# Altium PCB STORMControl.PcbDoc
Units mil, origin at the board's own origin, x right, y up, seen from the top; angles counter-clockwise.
Board outline 3700 x 3210 mil, 2 copper layers (Top Layer, Bottom Layer); 76 components, 43 nets, 234 pads, 25 vias.
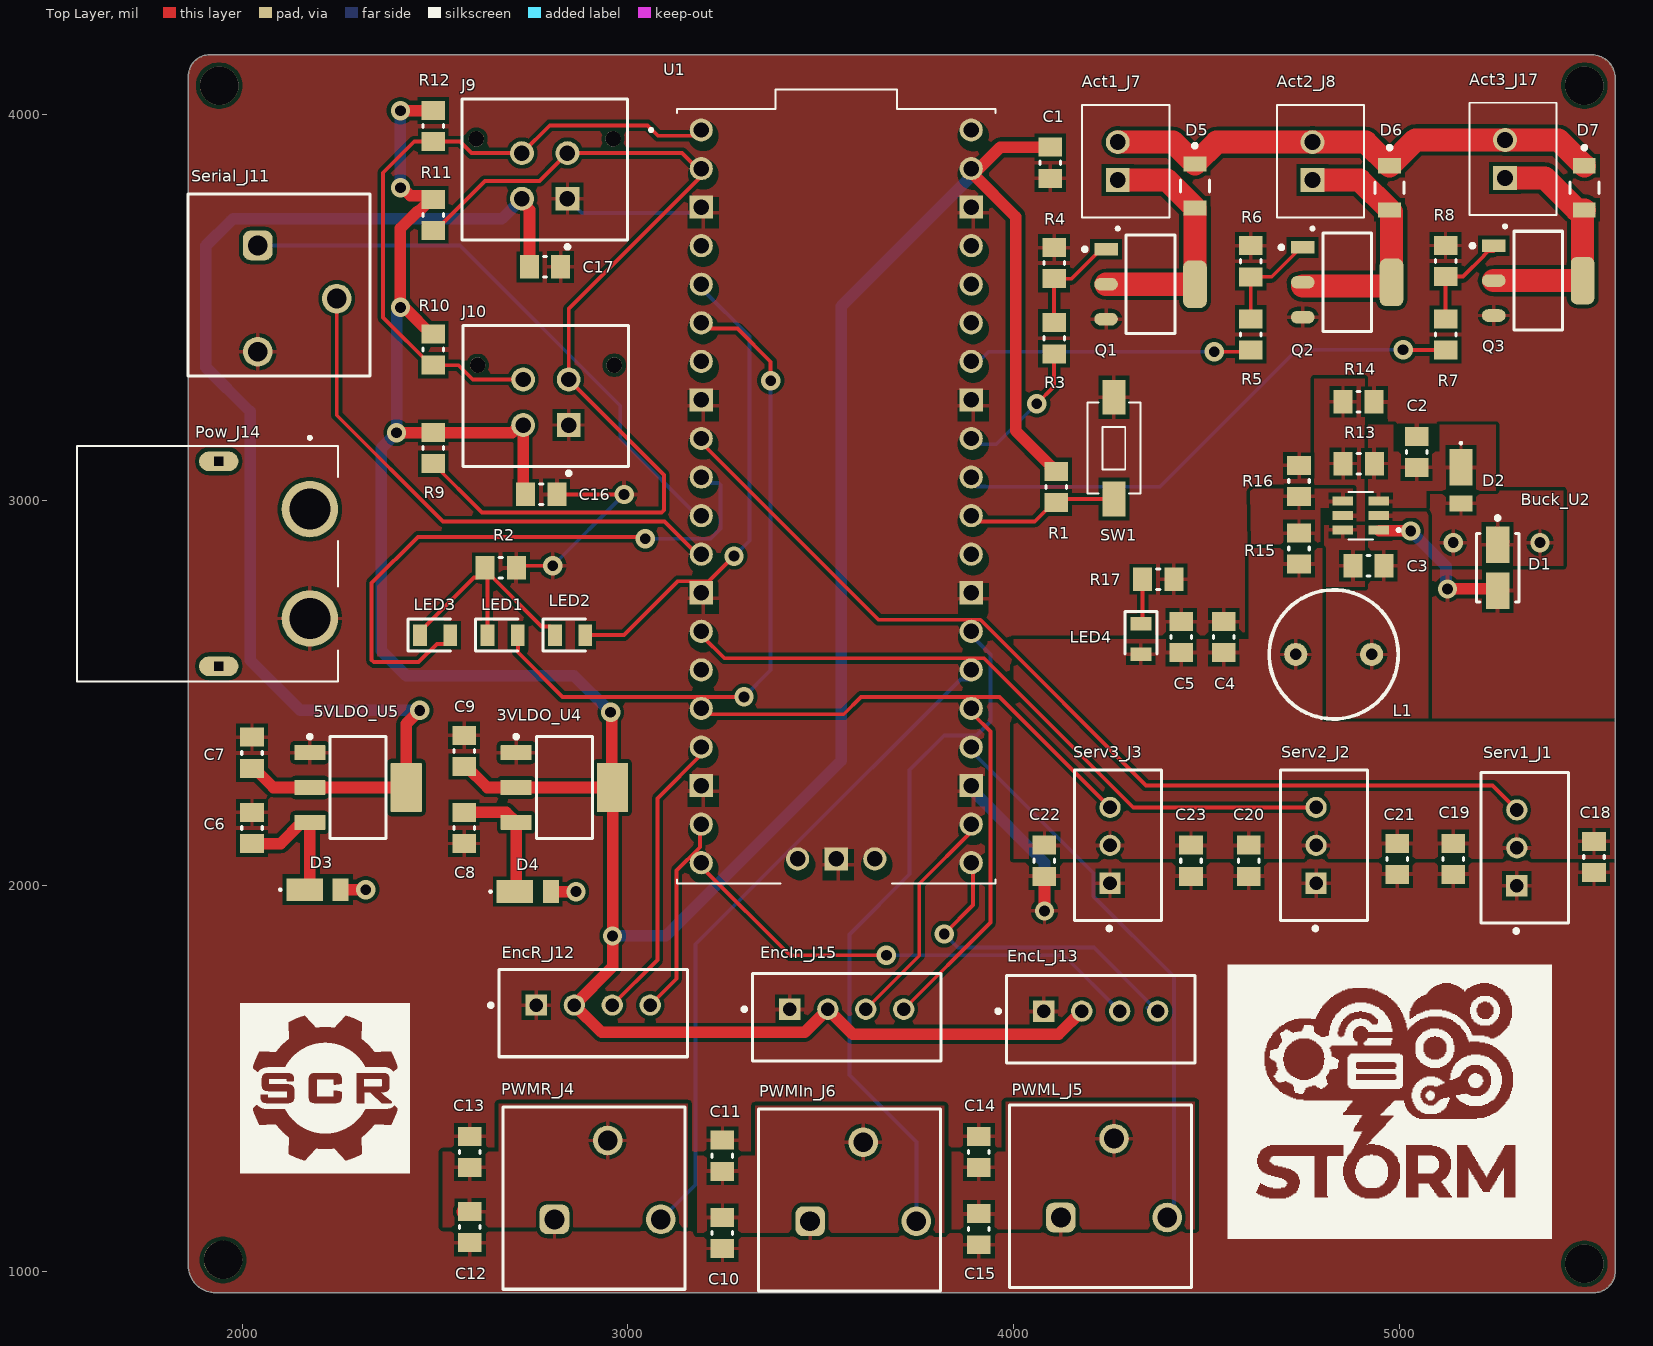
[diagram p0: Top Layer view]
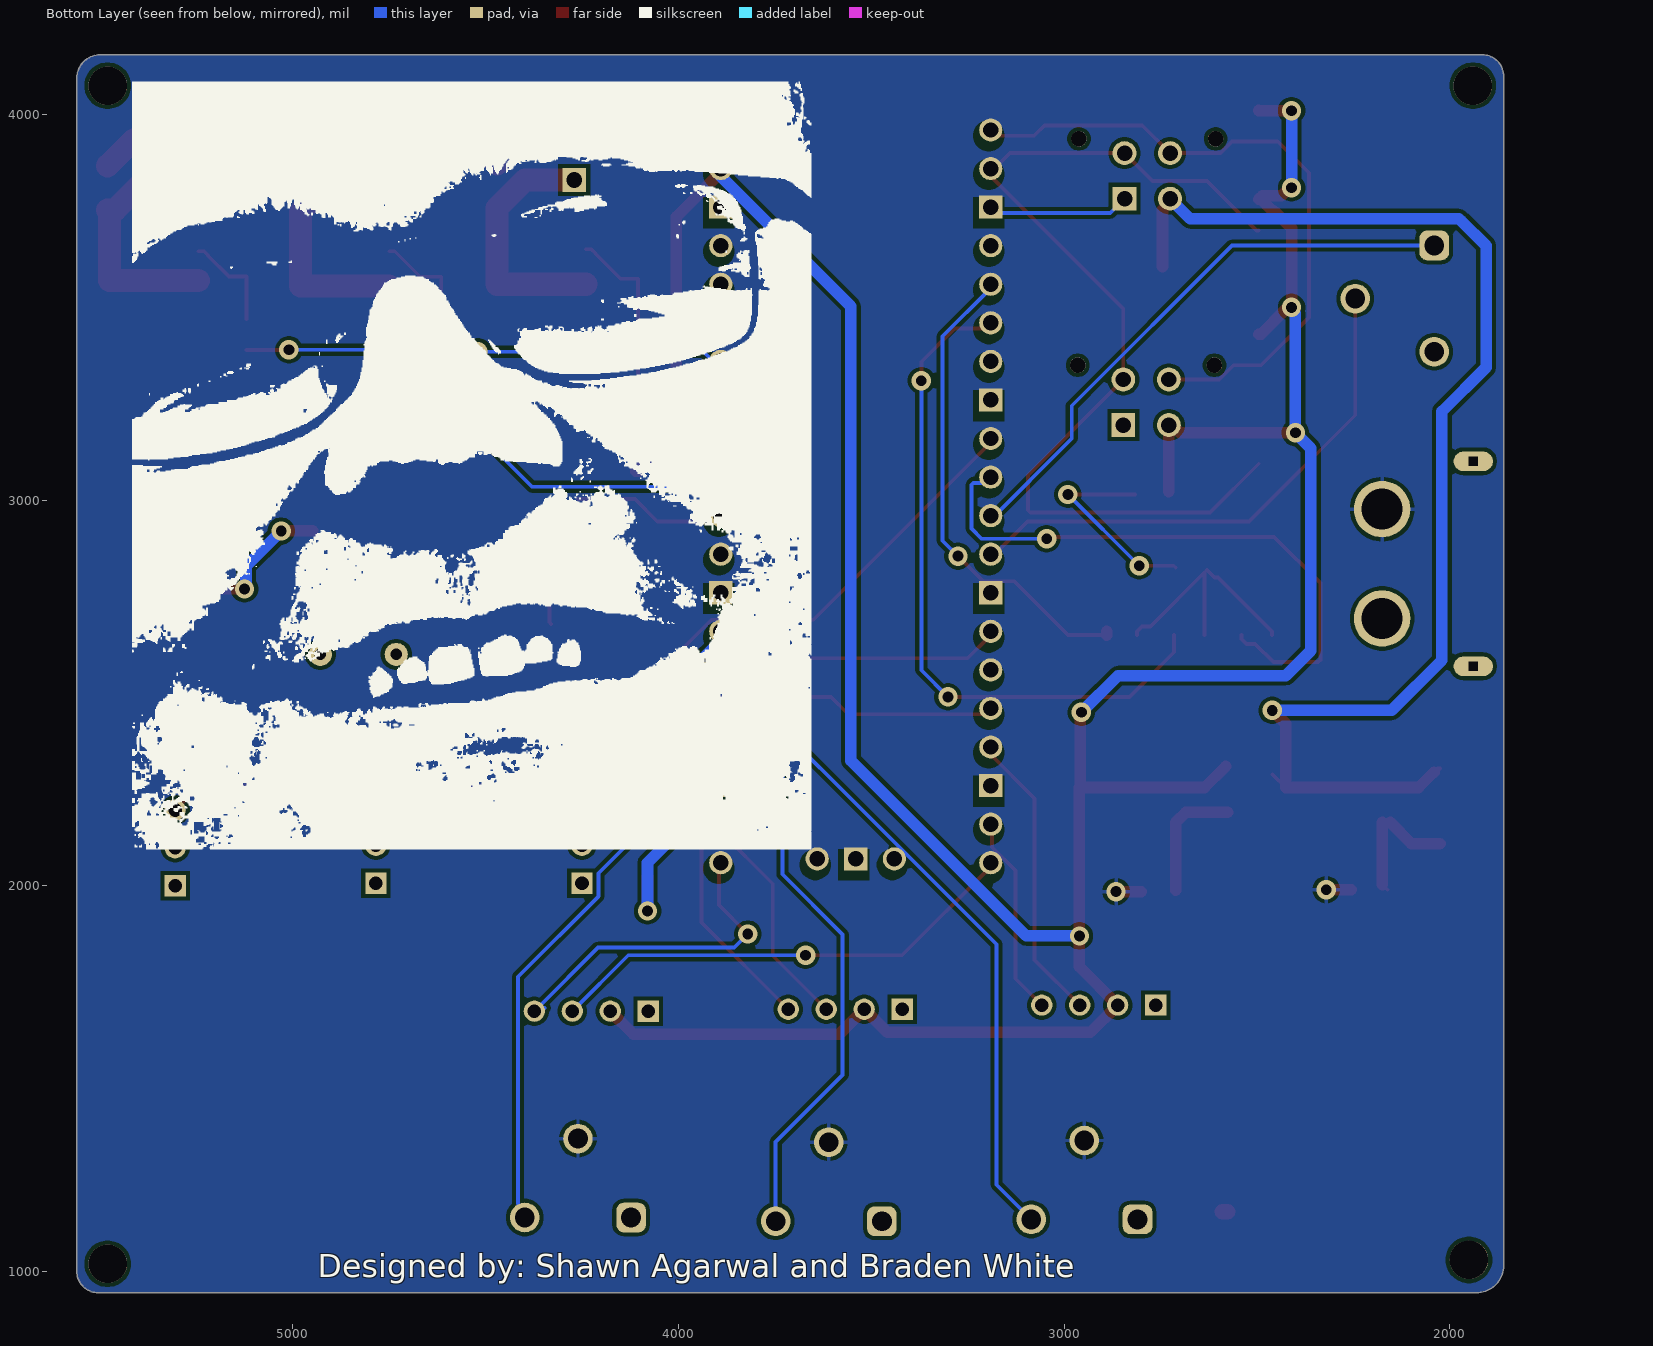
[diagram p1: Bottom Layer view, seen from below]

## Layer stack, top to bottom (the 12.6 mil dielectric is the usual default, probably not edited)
Top Solder: solder mask 0.4, Solder Resist, Dk 3.5
Top Layer: signal copper 1.4
Dielectric 1: dielectric 12.6, FR-4, Dk 4.8
Bottom Layer: signal copper 1.4
Bottom Solder: solder mask 0.4, Solder Resist, Dk 3.5

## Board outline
1860,1015 1860,4100 cw(c1915,4100) 1915,4155 5500,4155 cw(c5500,4095) 5560,4095 5560,1000 cw(c5505,1000) 5505,945 1930,945 cw(c1930,1015)

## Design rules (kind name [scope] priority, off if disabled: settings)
BoardOutlineClearance [All] p1: gap=0.75 ignorepadtopadclearanceinfootprint=FALSE
Clearance [All] p1: gap=10 ignorepadtopadclearanceinfootprint=FALSE
PolygonConnect [All] p1: connectstyle=Relief reliefconductorwidth=10 reliefentries=4 polygonreliefangle="90 Angle" airgapwidth=10
RoutingVias [All] p1: holewidth=28 width=50 viastyle="Through Hole" minholewidth=28 minwidth=50 maxholewidth=28 maxwidth=50
SolderMaskExpansion SolverMaskExpansion_Via [IsVia] p1: expansion=4 istentingtop=TRUE
SolderMaskExpansion [All] p2: expansion=4 istentingtop=FALSE
SupplyNets "Schematic Supply Nets_4" [InNet('+5')] p1: voltage=0.000
SupplyNets "Schematic Supply Nets_3" [InNet('+7')] p2: voltage=0.000
SupplyNets "Schematic Supply Nets_2" [InNet('GND')] p3: voltage=0.000
SupplyNets "Schematic Supply Nets_1" [InNet('+3.3')] p4: voltage=0.000
SupplyNets "Schematic Supply Nets" [InNet('+12')] p5: voltage=0.000
Width [All] p1: maxlimit=80 minlimit=10 preferedwidth=10 minimp=50.000000 maximp=50.000000 favimp=50.000000
30 further rules are at their usual default settings.

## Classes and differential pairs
component class U_power: 3VLDO_U4 5VLDO_U5 Buck_U2 C2 C3 C4 C5 C6 C7 C8 C9 D1 D2 D3 D4 L1 LED4 R13 R14 R15 R16 R17
component class U_pico: C1 LED1 LED2 LED3 Q1 Q2 Q3 R1 R2 R3 R4 R5 R6 R7 R8 SW1 U1
component class U_interfaces: Act1_J7 Act2_J8 Act3_J17 C10 C11 C12 C13 C14 C15 C16 C17 C18 C19 C20 C21 C22 C23 D5 D6 D7 EncIn_J15 EncL_J13 EncR_J12 J9 J10 Pow_J14 PWMIn_J6 PWML_J5 PWMR_J4 R9 R10 R11 R12 Serial_J11 Serv1_J1 Serv2_J2 Serv3_J3

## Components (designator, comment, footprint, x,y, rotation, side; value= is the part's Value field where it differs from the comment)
3VLDO_U4 "REG1117-3.3" DCY0004A_M 2835,2255 r0 top
5VLDO_U5 "REG1117-5" DCY0004A_M 2300,2255 r0 top
Act1_J7 "B2B-XH-A_(LF)(SN)" JST_B2B-XH-A_(LF)(SN) 4290.67,3879.21 r270 top
Act2_J8 "B2B-XH-A_(LF)(SN)" JST_B2B-XH-A_(LF)(SN) 4795.67,3879.21 r270 top
Act3_J17 "B2B-XH-A_(LF)(SN)" JST_B2B-XH-A_(LF)(SN) 5295,3885 r270 top
Buck_U2 "AP62301WU-7" SOT95P280X100-6N 4900,2960 r180 top
C1 "GENERIC CAPACITOR" FP-C0805C-DG-IPC_C 4095,3875 r270 top
C2 "GENERIC CAPACITOR" FP-C0805C-DG-IPC_C 5045,3125 r90 top
C3 "GENERIC CAPACITOR" FP-C0805C-DG-IPC_C 4920,2830 r0 top
C4 "GENERIC CAPACITOR" FP-C0805C-DG-IPC_C 4545,2645 r90 top
C5 "GENERIC CAPACITOR" FP-C0805C-DG-IPC_C 4435,2645 r90 top
C6 "GENERIC CAPACITOR" FP-C0805C-DG-IPC_C 2025,2150 r90 top
C7 "GENERIC CAPACITOR" FP-C0805C-DG-IPC_C 2025,2345 r90 top
C8 "GENERIC CAPACITOR" FP-C0805C-DG-IPC_C 2575,2150 r270 top
C9 "GENERIC CAPACITOR" FP-C0805C-DG-IPC_C 2575,2350 r90 top
C10 "GENERIC CAPACITOR" FP-C0805C-DG-IPC_C 3245,1100 r270 top
C11 "GENERIC CAPACITOR" FP-C0805C-DG-IPC_C 3245,1300 r90 top
C12 "GENERIC CAPACITOR" FP-C0805C-DG-IPC_C 2590,1115 r270 top
C13 "GENERIC CAPACITOR" FP-C0805C-DG-IPC_C 2590,1310 r90 top
C14 "GENERIC CAPACITOR" FP-C0805C-DG-IPC_C 3910,1310 r90 top
C15 "GENERIC CAPACITOR" FP-C0805C-DG-IPC_C 3910,1109.65 r270 top
C16 "GENERIC CAPACITOR" FP-C0805C-DG-IPC_C 2775,3015 r0 top
C17 "GENERIC CAPACITOR" FP-C0805C-DG-IPC_C 2785,3605 r0 top
C18 "GENERIC CAPACITOR" FP-C0805C-DG-IPC_C 5505,2075 r270 top
C19 "GENERIC CAPACITOR" FP-C0805C-DG-IPC_C 5140,2070 r270 top
C20 "GENERIC CAPACITOR" FP-C0805C-DG-IPC_C 4610,2065 r270 top
C21 "GENERIC CAPACITOR" FP-C0805C-DG-IPC_C 4995,2070 r270 top
C22 "GENERIC CAPACITOR" FP-C0805C-DG-IPC_C 4080,2065 r270 top
C23 "GENERIC CAPACITOR" FP-C0805C-DG-IPC_C 4460,2065 r270 top
D1 "SMAJ13CA-E3/61" VISH-DO-214AC-2_N 5255,2824.96 r270 top
D2 "SBR3U60P1Q-7" SBR3U60P1Q7 5160,3051.54 r90 top
D3 "SBR3U60P1Q-7" SBR3U60P1Q7 2195,1990 r180 top
D4 "SBR3U60P1Q-7" SBR3U60P1Q7 2740,1985 r180 top
D5 "1N5819HW1-7-F" FP-SOD123F_Type_B-MFG 4470,3815 r270 top value=30pF
D6 "1N5819HW1-7-F" FP-SOD123F_Type_B-MFG 4975,3810 r270 top value=30pF
D7 "1N5819HW1-7-F" FP-SOD123F_Type_B-MFG 5480,3810 r270 top value=30pF
EncIn_J15 "B4B-XH-A(LF)(SN)" FP-B4B-XH-A_LF_SN-MFG 3567.36,1659.33 r180 top
EncL_J13 "B4B-XH-A(LF)(SN)" FP-B4B-XH-A_LF_SN-MFG 4225.79,1654.33 r180 top
EncR_J12 "B4B-XH-A(LF)(SN)" FP-B4B-XH-A_LF_SN-MFG 2910,1670 r180 top
J9 "43045-0414" FP-43045-0414-MFG 2784.06,3857.28 r0 top
J10 "43045-0414" FP-43045-0414-MFG 2787.17,3270.28 r0 top
L1 "RLB0913" "New footprint 1" 4830,2600 r180 top
LED1 "AP2012SRCPRV" LEDC2012X110N 2675,2650 r0 top
LED2 "AP2012SRCPRV" LEDC2012X110N 2850,2650 r0 top
LED3 "AP2012SRCPRV" LEDC2012X110N 2500,2650 r0 top
LED4 "AP2012SRCPRV" LEDC2012X110N 4330,2640 r270 top
Pow_J14 "XT60PW-F" AMASS_XT60PW-F 2175,2835 r270 top
PWMIn_J6 "691412120003B" 691412120003B 3574.57,1185.39 r0 top
PWML_J5 "691412120003B" 691412120003B 4225,1195 r0 top
PWMR_J4 "691412120003B" 691412120003B 2911.77,1190.12 r0 top
Q1 "ZXMN4A06GTA" FP-SOT223-IPC_C 4355,3560 r0 top
Q2 "ZXMN4A06GTA" FP-SOT223-IPC_C 4864.79,3565 r0 top
Q3 "ZXMN4A06GTA" FP-SOT223-IPC_C 5360.21,3569.45 r0 top
R1 "RES 0805" RESC2013X50X30ML20T20 4110,3034.65 r90 top
R2 "RES 0805" RESC2013X50X30ML20T20 2670,2825 r0 top
R3 "RES 0805" RESC2013X50X30ML20T20 4105,3420 r90 top
R4 "RES 0805" RESC2013X50X30ML20T20 4105,3614.65 r270 top
R5 "RES 0805" RESC2013X50X30ML20T20 4615,3430 r90 top
R6 "RES 0805" RESC2013X50X30ML20T20 4615,3619.65 r270 top
R7 "RES 0805" RESC2013X50X30ML20T20 5120,3429.65 r90 top
R8 "RES 0805" RESC2013X50X30ML20T20 5120,3620 r270 top
R9 "RES 0805" RESC2013X50X30ML20T20 2495,3135 r90 top
R10 "RES 0805" RESC2013X50X30ML20T20 2495,3390.35 r90 top
R11 "RES 0805" RESC2013X50X30ML20T20 2495,3740 r90 top
R12 "RES 0805" RESC2013X50X30ML20T20 2495,3970.35 r90 top
R13 "RES 0805" RESC2013X50X30ML20T20 4895,3095 r180 top
R14 "RES 0805" RESC2013X50X30ML20T20 4894.65,3255 r180 top
R15 "RES 0805" RESC2013X50X30ML20T20 4740,2874.65 r270 top
R16 "RES 0805" RESC2013X50X30ML20T20 4740,3050 r270 top
R17 "RES 0805" RESC2013X50X30ML20T20 4375,2795 r180 top
Serial_J11 "691412120003B" 691412120003B 2095.12,3558.23 r270 top
Serv1_J1 "B3B-XH-A(LF)(SN)" FP-B3B-XH-A_LF_SN-MFG 5325.67,2098.43 r90 top
Serv2_J2 "B3B-XH-A(LF)(SN)" FP-B3B-XH-A_LF_SN-MFG 4805,2105 r90 top
Serv3_J3 "B3B-XH-A(LF)(SN)" FP-B3B-XH-A_LF_SN-MFG 4270.67,2105 r90 top
SW1 "" 434111050826 4260,3135 r270 top
U1 "RP2040 PICO" "RP2040 Pico footprint w/ pins" 3547.05,2917.35 r0 top

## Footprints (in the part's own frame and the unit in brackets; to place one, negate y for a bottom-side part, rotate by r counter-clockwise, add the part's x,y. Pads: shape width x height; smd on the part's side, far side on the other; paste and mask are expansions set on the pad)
434111050826 [mm] "6.0*3.5mm vertical type, SMD, height 5.0mm, white actuator, 260gf, T&R"
  rect 2.3x1.5 smd: 1(-3.35,0) 2(3.35,0)
  silkscreen extent -3,-1.75 3,1.75, body extent -4,-1.75 4,1.75, height 5
691412120003B [mm] "3,5mm - Spring clamp/Screw less - 45¡ã entry - 03p"
  rrect50% 1.95x1.95 hole 1.3: 1(-2.6,-1.4)
  round 1.95 hole 1.3: 2(0.9,3.8) 3(4.4,-1.4)
  silkscreen extent -6,-6 6,6, body extent -6,-6 6,6, height 12.85
AMASS_XT60PW-F [mm]
  round 3.716 hole 2.7: 1(-3.6,0) 2(3.6,0)
  oval 1.3x2.6 hole 0.6 square: S1(-6.75,-6) S2(6.75,-6)
  silkscreen extent -8.4,-15.35 7.75,1.85
DCY0004A_M [mm] "SOT223, 4-Leads, Body 6.7x3.7mm, Pitch 2.3mm, IPC Low Density"
  rrect10% 2.05x1 smd: 1(-3.175,2.3) 2(-3.175,0) 3(-3.175,-2.3)
  rrect5% 2.05x3.25 smd: 4(3.175,0)
  silkscreen extent -3.3,-3.35 1.85,3.47
FP-43045-0414-MFG [mm]
  rect 1.57x1.57 hole 1.02 paste-2539.97 mask+0: 1(1.5,-1.915)
  round 1.57 hole 1.02 paste-2539.97 mask+0: 2(-1.5,-1.915) 3(1.5,1.085) 4(-1.5,1.085)
  round 1.02 hole 1.02 unplated paste-2539.97 mask+0: ""(-4.5,2.025) ""(4.5,2.025)
  silkscreen extent -5.45,-5.21 5.45,4.63, body extent -5.55,-4.73 5.55,4.73, height 0.25
FP-B3B-XH-A_LF_SN-MFG [mm]
  rect 1.4x1.4 hole 0.9 paste-2539.97 mask+0: 1(-2.5,0.525)
  round 1.4 hole 0.9 paste-2539.97 mask+0: 2(0,0.525) 3(2.5,0.525)
  silkscreen extent -5.6,-2.88 4.95,2.88, body extent -5.05,-2.98 5.05,2.98, height 0.25
FP-B4B-XH-A_LF_SN-MFG [mm]
  rect 1.4x1.4 hole 0.9 paste-2539.97 mask+0: 1(3.75,-0.525)
  round 1.4 hole 0.9 paste-2539.97 mask+0: 2(1.25,-0.525) 3(-1.25,-0.525) 4(-3.75,-0.525)
  silkscreen extent -6.2,-2.88 6.87,2.88, body extent -6.3,-2.98 6.3,2.98, height 0.25
FP-C0805C-DG-IPC_C [mm]
  rect 1.25x1.55 smd: 1(-1.025,0) 2(1.025,0)
  silkscreen extent -0.1,-0.67 0.1,0.67, body extent -1.1,-0.72 1.1,0.72, height 0.5
FP-SOD123F_Type_B-MFG [mm]
  rect 1x1.5 smd paste+0 mask+0: 1(-1.45,0) 2(1.45,0)
  silkscreen extent -2.77,-0.95 0.38,0.95, body extent -2.05,-1.05 2.05,1.05, height 0.25
FP-SOT223-IPC_C [mm]
  rect 1.56x0.832 smd paste+0 mask+0: 1(-2.926,2.3)
  rrect100% 1.56x0.832 smd paste+0 mask+0: 2(-2.926,0) 3(-2.926,-2.3)
  rrect53% 1.56x3.132 smd paste+0 mask+0: 4(2.926,0)
  silkscreen extent -4.45,-3.25 1.6,3.25, body extent -3.81,-3.35 3.81,3.35, height 0.25
JST_B2B-XH-A_(LF)(SN) [mm]
  rect 1.575x1.575 / inner round 1.575 / far side rect 1.575x1.575 hole 1.05: 1(1.25,-0.525)
  round 1.575 hole 1.05: 2(-1.25,-0.525)
  silkscreen extent -3.7,-2.88 4.54,2.88, body extent -3.7,-2.88 3.7,2.88, height 7
LEDC2012X110N [mm]
  rect 0.9x1.4 smd: 1(-1,0) 2(1,0)
  silkscreen extent -1.8,-1.05 1,1.05
"New footprint 1" [mil]
  round 60 hole 30: 1(-98.43,0) 2(98.43,0)
  silkscreen extent -167,-167 167,167
RESC2013X50X30ML20T20 [mm] "Chip Resistor, 2-Leads, Body 2.00x1.25mm, IPC Low Density"
  rect 1.25x1.55 smd: 1(-1.025,0) 2(1.025,0)
  silkscreen extent -0.1,-0.67 0.1,0.67, body extent -1.1,-0.72 1.1,0.72, height 0.5
"RP2040 Pico footprint w/ pins" [mil]
  round 60 hole 40: 1(-357.05,1042.65) 2(-357.05,942.65) 4(-357.05,742.65) 5(-357.05,642.65) 6(-357.05,542.65) 7(-357.05,442.65) 9(-357.05,242.65) 10(-357.05,142.65) 11(-357.05,42.65) 12(-357.05,-57.35) 14(-357.05,-257.35) 15(-357.05,-357.35) 16(-357.05,-457.35) 17(-357.05,-557.35) 19(-357.05,-757.35) 20(-357.05,-857.35) 21(342.95,-857.35) 22(342.95,-757.35) 24(342.95,-557.35) 25(342.95,-457.35) 26(342.95,-357.35) 27(342.95,-257.35) 29(342.95,-57.35) 30(342.95,42.65) 31(342.95,142.65) 32(342.95,242.65) 34(342.95,442.65) 35(342.95,542.65) 36(342.95,642.65) 37(342.95,742.65) 39(342.95,942.65) 40(342.95,1042.65) D1(-107.05,-847.35) D3(92.95,-847.35)
  rect 60x60 hole 40: 3(-357.05,842.65) 8(-357.05,342.65) 13(-357.05,-157.35) 18(-357.05,-657.35) 23(342.95,-657.35) 28(342.95,-157.35) 33(342.95,342.65) 38(342.95,842.65) D2(-7.05,-847.35)
  silkscreen extent -491,-911 406,1148
SBR3U60P1Q7 [mm]
  rect 2.4x1.5 smd: 1(0.85,0)
  rect 1.05x1.5 smd: 2(-1.525,0)
  silkscreen extent 2.4,-0.05 2.5,0.05
SOT95P280X100-6N [mm]
  rect 1.34x0.59 smd: 1(-1.19,0.95) 2(-1.19,0) 3(-1.19,-0.95) 4(1.19,-0.95) 5(1.19,0) 6(1.19,0.95)
  silkscreen extent -2.6,-1.57 0.8,1.57, body extent -1.4,-1.45 1.4,1.45, height 1
VISH-DO-214AC-2_N [mm] "DO-214AC, 2-Leads, Body 4.5x2.79mm, IPC Medium Density"
  rect 2.4x1.55 smd: 1(-1.525,0) 2(1.525,0)
  silkscreen extent -3.4,-1.4 2.25,1.4, body extent -2.25,-1.4 2.25,1.39, height 2.29

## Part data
3VLDO_U4 5VLDO_U5: library part CMP-019-00049-4, "LDO Regulator Pos 3.3V 0.8A 4-Pin(3+Tab) SOT-223 Rail"
Act1_J7 Act2_J8 Act3_J17: library part CMP-002-00025-1, "Connector Header Through Hole 2 position 0.098 (2.50mm)", Case/Package=None
Buck_U2: library part CMP-142-000001-1, "Converter, buck, 4.2V to 18V input, 3A low IQ synchronous, DC-DC, TSOT26", Package="TSOT-23-6 Diodes Inc."
C1 C2 C3 C4 C5 C6 C7 C8 C9 C10 C11 C12 C13 C14 C15 C16 C17 C18 C19 C20 C21 C22 C23: library part CMP-001-00083-4, "GENERIC CAPACITOR 0805 or 0603(1608)"
D1: library part CMP-0548-00189-2, "Transient Voltage Suppressor, 6.40 to 231 V, 13 V Stand-off Voltage, Bi-Directional, -55 to 155 degC, 2-pin DO-214AC, Pb-Free, Tape and Reel", Manufacturer="Vishay Semiconductor", Operating Junction and Storage Temperature Range="-55 to 150 degC"
D2 D3 D4: library part CMP-077-000000-3, "Schottky Diodes & Rectifiers 3A SBR 60Vrrm 3A 0.62Vf 100Ir", Manufacturer_Name="Diodes Inc.", Mouser Part Number=621-SBR3U60P1Q-7
D5 D6 D7: library part CMP-12791-000028-1, "DIODE SBR 40V 1A SOD123F", Capacitance=30pF, Forward Current=1A, Manufacturer="Diodes Inc.", Max Junction Temp=+125°C, Max Repetitive Reverse Voltage=40V, Max Surge Forward Current=30A, Package="SOD123F (Type B)", Peak Reverse Current=0.5mA, Temperature="-55°C to +125°C", Temperature Range Low=-55°C
EncIn_J15 EncL_J13 EncR_J12: library part CMP-17439-000250-1, "CONN HEADER VERT 4POS 2.5MM", Color=Natural, Contact Resistance=20mR, Current Rating=3A, Flammability Rating="UL94 V-0", Housing Color=White, Insulation Resistance=1GR, Max Operating Temperature=85°C, Max Voltage Rating (AC)=250V, Min Operating Temperature=-25°C, Package Quantity=500
J9 J10: library part CMP-04776-000520-1, "CONN HEADER VERT 4POS 3MM", Case/Package=0414, Color=Black, Contact Resistance=10mR, Current Rating=5A, Flammability Rating="UL94 V-0", Insulation Resistance=1GR, Max Operating Temperature=105°C, Max Voltage Rating (DC)=250.25kV, Min Operating Temperature=-40°C, Package Quantity=2232, Voltage Rating=600V, Voltage Rating (DC)=250V
L1: library part CMP-006-00000-1, "RLB0913 Series Radial Lead Inductor", Inductor Application="DC-DC CONVERTER", Max Operating Temperature=125°C, Min Operating Temperature=-55°C, Self Resonant Frequency=79MHz, Tolerance=10%
LED1 LED2 LED3 LED4: library part CMP-013-000000-2, "RED LED", Manufacturer_Name=Kingbright, Manufacturer_Part_Number=AP2012SGD3, Mouser2 Part Number=604-AP2012SGD3
Pow_J14: library part CMP-002-00003-4, "Socket DC Supply Connector Female", Case/Package=Package
PWMIn_J6 PWML_J5 PWMR_J4 Serial_J11: library part CMP-1502-02904-2
Q1 Q2 Q3: library part CMP-016-00004-2, "Power Field-Effect Transistor, 5A I(D), 40V, 0.05ohm, 1-Element, N-Channel, Silicon, Metal-oxide Semiconductor FET", Max Operating Temperature=150°C
R1 R2 R3 R4 R5 R6 R7 R8 R9 R10 R11 R12 R13 R14 R15 R16 R17: library part CMP-009-00177-3, "Surface Mount 0805 Resistor"
Serv1_J1 Serv2_J2 Serv3_J3: library part CMP-17439-000014-3, "CONN HEADER VERT 3POS 2.5MM", Color=Natural, Contact Resistance=20mR, Current Rating=3A, Flammability Rating="UL94 V-0", Housing Color=White, Insulation Resistance=1GR, Max Operating Temperature=85°C, Max Voltage Rating (AC)=250V, Min Operating Temperature=-25°C
SW1: library part CMP-011-00013-1, "Switch Tactile Button Spst-no 0.05A 12V"
U1: library part CMP-027-000000-14, "RP2040 Raspberry Pi Pico - ARM Cortex-M0+ MCU 32-Bit Embedded Evaluation Board", Package=None

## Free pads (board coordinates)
  round 100 hole 100: ""(1940,4075) ""(1950,1030) ""(5480,1020) ""(5480,4075)

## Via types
v1: diameter 50, hole 28, Top Layer to Bottom Layer, tented both sides, 25 vias

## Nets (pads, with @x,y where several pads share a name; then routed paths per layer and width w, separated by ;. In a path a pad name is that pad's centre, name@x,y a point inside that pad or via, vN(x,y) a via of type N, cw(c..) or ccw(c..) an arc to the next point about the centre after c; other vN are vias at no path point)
+3.3: 3VLDO_U4.2 3VLDO_U4.4 C1.1 C9.1 C16.1 EncIn_J15.2 EncL_J13.2 EncR_J12.2 J10.2 R1.2 R9.2 R10.2 R11.2 R12.2 U1.39 | length 9075
  Top Layer w10: C9.1 C9.1@2580.91,2309.65 ; C16.1@2728.11,3021.54 C16.1
  Top Layer w30: v1(2400,3175) 2400.18,3175.18 2494.82,3175.18 R9.2 2699.97,3175.35 2719.5,3194.88 J10.2 C16.1@2728.11,3021.54 ; v1(2410,3810) 2415.41,3810 2435.45,3789.96 2485.39,3789.96 R11.2 2489.09,3780.35 2458.27,3749.53 2454.42,3749.53 2410,3705.12 v1(2410,3500) 2413.83,3496.17 2423.63,3496.17 2489.09,3430.71 R10.2 ; v1(2410,4010) 2410.35,4010.35 2494.65,4010.35 R12.2 ; C9.1@2580.91,2309.65 2635.55,2255 3VLDO_U4.2 3VLDO_U4.4 ; v1(2955,2450) 2957.5,2447.5 2957.5,2257.5 3VLDO_U4.4 ; C1.1 3965.35,3915.35 3895,3845 4005,3735 4005,3180 4094.49,3090.51 4094.49,3084.61 4104.09,3075 R1.2 ; EncL_J13.2 4116.57,1615 3583.15,1615 EncIn_J15.2 3458.15,1620 2931.46,1620 EncR_J12.2 2960,1789.88 v1(2960,1870) 3VLDO_U4.4
  Bottom Layer w30: v1(2410,3500) 2410,3494.59 2400,3484.59 v1(2400,3175) 2360,3135 2360,2610 2425,2545 2860,2545 v1(2955,2450) ; v1(2410,3810) v1(2410,4010) ; v1(2960,1870) 3097.78,1870 3552.65,2324.87 3552.65,3502.65 U1.39@3895,3845
+5: 5VLDO_U5.2 5VLDO_U5.4 C7.1 C17.1 J9.2 | length 3354.5
  Top Layer w10: C7.1 2030.35,2304.65 2040,2295 C7.1@2040.55,2295 ; 5VLDO_U5.4 5VLDO_U5.4@2459.17,2289.17
  Top Layer w30: C7.1@2040.55,2295 2080.55,2255 5VLDO_U5.2 5VLDO_U5.4 2425,2420 v1(2460,2455) ; J9.2 2725,3773.28 2744.65,3753.64 C17.1
  Bottom Layer w10: 1970,3724.14 1975.86,3730
  Bottom Layer w30: 1970,3724.14 1905.5,3659.64 1905.5,3344.5 2020,3230 2020,2585 2150,2455 v1(2460,2455) ; 1975.86,3730 2673.11,3730 J9.2
+7: C4.1 C5.1 C18.1 C19.1 C20.1 C21.1 C22.1 C23.1 L1.2 LED4.2 R15.2 Serv1_J1.2 Serv2_J2.2 Serv3_J3.2
+12: Act1_J7.2 Act2_J8.2 Act3_J17.2 C10.1 C11.1 C12.1 C13.1 C14.1 C15.1 D1.1 D2.2 D3.2 D4.2 D5.1 D6.1 D7.1 Pow_J14.1 PWMIn_J6.2 PWML_J5.2 PWMR_J4.2 | length 1539.5
  Top Layer w10: C12.1@2575.35,1170 C12.1
  Top Layer w30: D3.2 v1(2320,1990) ; D4.2 v1(2865,1985)
  Top Layer w40: C12.1@2575.35,1155.35 C12.1 ; PWMR_J4.2@2937.25,1339.72 PWMR_J4.2
  Top Layer w60: PWMIn_J6.2@3605.46,1335 PWMIn_J6.2 ; PWML_J5.2@4255.89,1344.61 PWML_J5.2 ; Act1_J7.2 4413.66,3928.43 D5.1 4526.34,3928.43 Act2_J8.2 4913.66,3928.43 D6.1 5042.13,3934.21 Act3_J17.2 5274.71,3933.83 5413.26,3933.83 D7.1 ; D1.1 D1.1@5255,2901.73 ; D1.1@5255,2889.49 D1.1@5255.51,2890
  other v1: 5140,2890 5365,2890
ACTUATOR_ONE_EN: R3.1 U1.32 | length 356.8
  Top Layer w10: v1(4060,3250) 4105,3295 R3.1
  Bottom Layer w10: U1.32@3895,3145 3955,3145 v1(4060,3250)
ACTUATOR_THREE_EN: R7.1 U1.31 | length 1376.5
  Top Layer w10: v1(5010,3390) 5010.71,3389.29 R7.1
  Bottom Layer w10: U1.31@3895,3045 3904.57,3035.43 3925.42,3035.43 3925.86,3035 4380,3035 4735,3390 v1(5010,3390)
ACTUATOR_TWO_EN: R5.1 U1.34 | length 738.5
  Top Layer w10: v1(4520,3385) 4610.35,3385 R5.1
  Bottom Layer w10: U1.34@3895,3345 3935,3385 v1(4520,3385)
GND: 3VLDO_U4.1 5VLDO_U5.1 Buck_U2.1 C1.2 C2.2 C4.2 C5.2 C6.2 C7.2 C8.2 C9.2 C10.2 C11.2 C12.2 C13.2 C14.2 C15.2 C16.2 C17.2 C18.2 C19.2 C20.2 C21.2 C22.2 C23.2 D1.2 EncIn_J15.1 EncL_J13.1 EncR_J12.1 J9.1 J10.1 Pow_J14.2 PWMIn_J6.1 PWML_J5.1 PWMR_J4.1 Q1.3 Q2.3 Q3.3 R2.2 R4.1 R6.1 R8.1 R14.1 R16.1 R17.1 Serial_J11.3 Serv1_J1.1 Serv2_J2.1 Serv3_J3.1 SW1.1 U1.3 U1.8 U1.13 U1.18 U1.23 U1.28 U1.33 U1.38 U1.D2 | length 1785.1
  Top Layer w10: R2.2 2715.35,2830 v1(2805,2830) ; C16.2 v1(2990,3015) ; Buck_U2.1 Buck_U2.1@4948.15,2921.3 ; v1@5028.7,2921.3 v1(5030,2920)
  Top Layer w30: v1(4080,1935) C22.2 ; Buck_U2.1@4948.15,2921.3 v1@5028.7,2921.3 ; v1(5125,2770) 5255,2770 D1.2
  Bottom Layer w10: v1(2805,2830) v1(2990,3015) ; J9.1 2880,3745 U1.3@3195,3745
  Bottom Layer w30: U1.23@3895,2245 4080,2060 v1(4080,1935) ; v1(5030,2920) 5121.17,2828.83 5121.17,2773.83 v1(5125,2770)
LED_A: LED1.2 U1.6 | length 1794.2
  Top Layer w10: LED1.2 2714.37,2605.63 2830,2490 v1(3300.86,2490) 3305,2490 v1@3307.08,2492.08 ; U1.6@3195,3445 3284.14,3445 3370,3359.14 v1(3370,3310)
  Bottom Layer w10: v1(3300.86,2490) 3370,2559.14 v1(3370,3310)
LED_B: LED2.2 U1.5 | length 1236.7
  Top Layer w10: LED2.2 2990,2650 3130,2790 3210,2790 v1(3275,2855)
  Top Layer w30: LED2.2 LED2.2@2889.37,2659.84
  Bottom Layer w10: U1.5@3195,3545 3315,3425 3315,2895 v1(3275,2855)
LED_C: LED3.2 U1.10 | length 1567
  Top Layer w10: LED3.2 2539.37,2640.16 2526.65,2627.44 2504.56,2627.44 2457.12,2580 2340.86,2580 2335,2585.86 2335,2785 2455,2905 v1@3045,2905
  Bottom Layer w10: v1(3045,2900) 3213.64,2900 3240,2926.36 3240,3040 3235,3045 U1.10@3195,3045
Net3VLDO_U4_3: 3VLDO_U4.3 C8.1 D4.1 | length 326.5
  Top Layer w10: D4.1 D4.1@2710,1988.46 ; 3VLDO_U4.3@2709.95,2164.5 3VLDO_U4.3
  Top Layer w30: C8.1 2684.65,2190.35 3VLDO_U4.3@2710,2165 ; D4.1@2710,1988.46 3VLDO_U4.3
Net5VLDO_U5_3: 5VLDO_U5.3 C6.1 D3.1 | length 352.7
  Top Layer w10: 5VLDO_U5.3@2154.33,2164.45 5VLDO_U5.3 ; D3.1 D3.1@2175,2003.46
  Top Layer w30: C6.1 2099.53,2109.65 5VLDO_U5.3@2154.33,2164.45 ; D3.1@2175,2003.46 5VLDO_U5.3
NetAct1_J7_1: Act1_J7.1 D5.2 Q1.2 Q1.4 | length 658.3
  Top Layer w60: Q1.2 Q1.4 4470.21,3757.71 D5.2 4397.91,3830 Act1_J7.1
NetAct2_J8_1: Act2_J8.1 D6.2 Q2.2 Q2.4 | length 662.4
  Top Layer w60: Q2.2@4749.79,3555 4980.21,3555 4980.21,3747.71 D6.2 4897.91,3830 Act2_J8.1
NetAct3_J17_1: Act3_J17.1 D7.2 Q3.2 Q3.4 | length 655.8
  Top Layer w60: Q3.2 Q3.4 5475.41,3748.33 D7.2 5460,3752.91 5377.13,3835.79 Act3_J17.1
NetBuck_U2_2: Buck_U2.2 C3.2 L1.1
NetBuck_U2_3: Buck_U2.3 C2.1 D2.1 R13.1
NetBuck_U2_4: Buck_U2.4 R15.1 R16.2
NetBuck_U2_5: Buck_U2.5 R13.2 R14.2
NetBuck_U2_6: Buck_U2.6 C3.1 | length 5.9
  Top Layer w10: C3.1 C3.1@4879.65,2835.91
NetEncIn_J15_3: EncIn_J15.3 U1.22 | length 580.3
  Top Layer w10: EncIn_J15.3 3755.32,1818.75 3755.32,2005.32 U1.22@3895,2145
NetEncIn_J15_4: EncIn_J15.4 U1.25 | length 876.8
  Top Layer w10: EncIn_J15.4 3940,1905 3940,2400 U1.25@3895,2445
NetEncL_J13_3: EncL_J13.3 U1.20 | length 1233.3
  Top Layer w10: U1.20@3195,2045 3420,1820 v1(3670,1820)
  Bottom Layer w10: v1(3670,1820) 4130,1820 EncL_J13.3
NetEncL_J13_4: EncL_J13.4 U1.21 | length 855.8
  Top Layer w10: v1(3820,1875) 3895,1950 U1.21@3895,2045
  Bottom Layer w10: v1(3820,1875) 3855,1840 4208.43,1840 EncL_J13.4@4364.79,1683.63 ; 4346.37,1683.63 EncL_J13.4@4364.79,1683.63 ; EncL_J13.4 EncL_J13.4@4364.79,1683.63
NetEncR_J12_3: EncR_J12.3 U1.17 | length 752
  Top Layer w10: EncR_J12.3 3076.64,1808.1 3076.64,2226.64 U1.17@3195,2345
NetEncR_J12_4: EncR_J12.4 U1.19 | length 511.2
  Top Layer w10: EncR_J12.4 3125.85,1758.88 3125.85,2039.49 3186.36,2100 3186.36,2136.36 U1.19@3195,2145
NetJ9_3: J9.3 J10.3 R9.1 R11.1 U1.2 | length 2576.5
  Top Layer w10: R9.1 2621.22,2968.43 3087.57,2968.43 3093.43,2974.29 3093.43,3065.78 J10.3 2846.22,3496.22 3195,3845 3140,3900 J9.3 2770.91,3827.8 2629.06,3827.8 2500.91,3699.65 R11.1
NetJ9_4: J9.4 J10.4 R10.1 R12.1 U1.1 | length 1721.9
  Top Layer w10: J10.4 2597.4,3312.99 2560.39,3350 R10.1 2489.09,3350 2365,3474.09 2365,3849.14 2445.86,3930 R12.1 2564.29,3930 2594.29,3900 J9.4 2797.09,3972.09 3050.54,3972.09 3077.62,3945 U1.1@3195,3945
NetLED1_1: LED1.1 LED2.1 LED3.1 R2.1 | length 656.3
  Top Layer w10: LED3.1 2460.63,2659.84 2600.28,2799.49 2610.04,2799.49 R2.1@2629.65,2819.09 ; LED1.1 2635.63,2813.11 2776.18,2672.56 2797.91,2672.56 2810.63,2659.84 LED2.1
NetLED4_1: LED4.1 R17.2 | length 117.6
  Top Layer w10: LED4.1 4334.65,2684.02 R17.2
NetPWMIn_J6_3: PWMIn_J6.3 U1.27 | length 1805.9
  Bottom Layer w10: PWMIn_J6.3 3747.8,1336.1 3574.02,1509.88 3574.02,1874.02 3730.19,2030.19 3730.19,2300.19 3820,2390 3903.64,2390 3940,2426.36 3940,2600 U1.27@3895,2645
NetPWML_J5_3: PWML_J5.3 U1.24 | length 1428.3
  Bottom Layer w10: U1.24@3895,2345 4207.44,2032.56 4207.44,1972.8 4415.98,1764.26 4415.98,1675 4415.98,1175.71 4398.23,1157.95 PWML_J5.3
NetPWMR_J4_3: PWMR_J4.3 U1.26 | length 1759.4
  Bottom Layer w10: PWMR_J4.3 3175,1225 3175,1848.64 3400.03,2073.67 3861.79,2535.43 3885.43,2535.43 U1.26@3895,2545
NetQ1_1: Q1.1 R3.2 R4.2 | length 281.1
  Top Layer w10: R3.2 R4.2 4150.51,3574.29 4214.09,3637.87 4214.09,3639.17 4225.47,3650.55 Q1.1
NetQ2_1: Q2.1 R5.2 R6.2 | length 271.2
  Top Layer w10: R5.2 R6.2 4669.21,3579.29 4735.47,3645.55 Q2.1@4749.79,3645.55
NetQ3_1: Q3.1 R7.2 R8.2 | length 262.3
  Top Layer w10: R7.2 R8.2 5165.51,3579.65 5219.09,3633.23 5219.09,3634.17 5230.47,3645.55 Q3.1@5244.79,3645.55
NetR1_1: R1.1 SW1.2 U1.30 | length 389.1
  Top Layer w10: U1.30@3895,2945 4054.8,2945 4112.91,3003.11 SW1.2
NetSerial_J11_1: Serial_J11.1 U1.11 | length 1501.2
  Bottom Layer w10: Serial_J11.1 2564.41,3660.59 2980,3245 2980,3160 U1.11@3195,2945
NetSerial_J11_2: Serial_J11.2 U1.12 | length 1408.2
  Top Layer w10: Serial_J11.2 2244.72,3220.28 2520,2945 3095,2945 U1.12@3195,2845
NetServ1_J1_3: Serv1_J1.3 U1.9 | length 2502.7
  Top Layer w10: U1.9@3195,3145 3650,2690 3913.64,2690 4343.64,2260 5241.85,2260 Serv1_J1.3
NetServ2_J2_3: Serv2_J2.3 U1.14 | length 1772.2
  Top Layer w10: U1.14@3195,2645 3250,2590 3923.61,2590 4310.19,2203.43 Serv2_J2.3
NetServ3_J3_3: Serv3_J3.3 U1.16 | length 1192.3
  Top Layer w10: U1.16@3195,2445 3559.66,2445 3604.66,2490 3963.43,2490 Serv3_J3.3
pads on no net: J9. J10. Pow_J14.S1 Pow_J14.S2 U1.4 U1.7 U1.15 U1.29 U1.35 U1.36 U1.37 U1.40 U1.D1 U1.D3

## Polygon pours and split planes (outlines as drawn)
+12 on Top Layer "+12_L01_P014" (solid, pour order 14): 5425,2830 5075,2830 5075,3025 5425,3025
NetBuck_U2_2 on Top Layer "NETBUCK_U2_2_L01_P013" (solid, pour order 13): 4805,2775 4805,2430 5075,2430 5075,2975 4914.97,2975 4914.88,2974.91 4914.88,2939.97 4983.09,2939.97 4983.04,2939.92 4983.04,2893.02 4921.02,2893.02 4920,2891.99 4920,2775
NetBuck_U2_6 on Top Layer "NETBUCK_U2_6_L01_P012" (solid, pour order 12): 4805,2935 4909.9,2935 4909.9,2775.1 4910,2775 4805,2775
NetBuck_U2_5 on Top Layer "NETBUCK_U2_5_L01_P011" (solid, pour order 11): 4780,3315 4910,3315 4910,2945 4820,2945 4820,2980 4885,2980 4885,3040 4780,3040
NetBuck_U2_3 on Top Layer "NETBUCK_U2_3_L01_P010" (solid, pour order 10): 5250,3025 5250,3195 5105,3195 5105,3125 4985,3125 4985,3195 4920,3195 4920,2980 5070,2980 5070,3025
NetBuck_U2_4 on Top Layer "NETBUCK_U2_4_L01_P008" (solid, pour order 8): 4613.96,3030 4805,3030 4880,3030 4880,2980 4795,2980 4795,2875 4616.11,2875
+7 on Top Layer "Top Layer-+7" (solid, pour order 5): 4000,2070 5560,2070 5560,2425 4800,2425 4800,2875 4610,2875 4610,2640 4000,2640
+12 on Top Layer "+12_L01_P004" (solid, pour order 4): 3840,1310 3840,1110 4050,1110 4470,1110 4470,1440 3980,1440 3980,1310
+12 on Top Layer "+12_L01_P003" (solid, pour order 3): 3180,1300 3180,1100 3400,1100 3820,1100 3820,1430 3330,1430 3330,1300
+12 on Top Layer "+12_L01_P000" (solid, pour order 0): 2520,1310 2520,1115 2725,1115 3155,1115 3155,1435 2665,1435 2665,1315 2665,1310
GND on Top Layer "GND_L01_P015" (solid, pour order 15): 1610,4310 5785,4310 5785,780 1610,780
+12 on Bottom Layer "+12_L02_P001" (solid, pour order 1): 1660,4300 5745,4300 5745,780 1660,780

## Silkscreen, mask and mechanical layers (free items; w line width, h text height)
Top Overlay:
  drawing of 14 lines, arcs and shapes, not listed
Bottom Overlay:
  drawing of 230 lines, arcs and shapes, not listed
  text "Designed by: Shawn Agarwal and Braden White" at 4935,984.99 h60
Mechanical 1:
  the board outline again, w10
